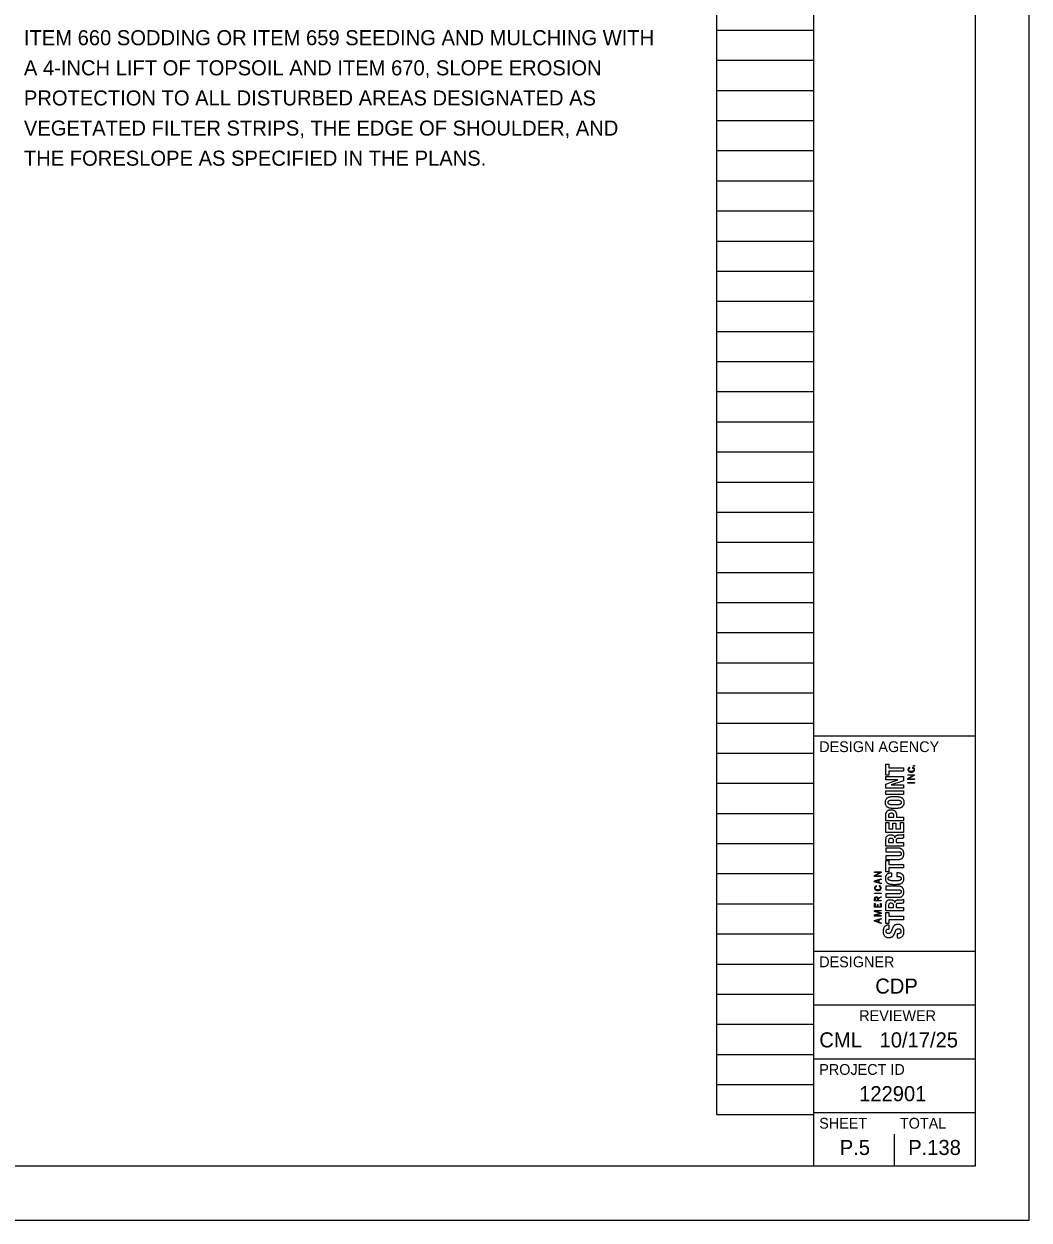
# Model space of a CAD drawing. Extents: x -19 to 64.6, y -1.7 to 22.
# Drawn here: x 24.66 to 34, y 0 to 11.12 of the extents above; entities that cross this region are included whole.
import ezdxf

# ---------------------------------------------------------------- set-up
doc = ezdxf.new("R2010")
doc.units = 0
for name, color, linetype in [('SH_Border', 7, 'Continuous'), ('SH_Cut_Line', 7, 'Continuous'), ('SH_Data', 7, 'Continuous'), ('SH_Text', 7, 'Continuous')]:
    doc.layers.add(name, color=color, linetype=linetype)

msp = doc.modelspace()

# ---------------------------------------------------------------- linework, layer by layer
at = {"layer": 'SH_Border'}
for p, q in [((32, 0.5), (32, 21.5)), ((32, 4.5), (33.5, 4.5)), ((32, 2.5), (33.5, 2.5)), ((32, 2), (33.5, 2)), ((32, 1.5), (33.5, 1.5)), ((32, 1), (33.5, 1))]:
    msp.add_line(p, q, dxfattribs=at)
msp.add_lwpolyline([(1.5, 21.5), (33.5, 21.5), (33.5, 0.5), (1.5, 0.5)], close=True, dxfattribs=at)
at = {"layer": 'SH_Cut_Line'}
msp.add_lwpolyline([(0, 0), (34, 0), (34, 22), (0, 22)], close=True, dxfattribs=at)
at = {"layer": 'SH_Data'}
for p, q in [((31.1, 0.98), (31.1, 21.14)), ((32, 0.98), (32, 21.14)), ((31.1, 11.06), (32, 11.06)), ((31.1, 10.78), (32, 10.78)), ((31.1, 10.5), (32, 10.5)), ((31.1, 10.22), (32, 10.22)), ((31.1, 9.94), (32, 9.94)), ((31.1, 9.66), (32, 9.66)), ((31.1, 9.38), (32, 9.38)), ((31.1, 9.1), (32, 9.1)), ((31.1, 8.82), (32, 8.82)), ((31.1, 8.54), (32, 8.54)), ((31.1, 8.26), (32, 8.26)), ((31.1, 7.98), (32, 7.98)), ((31.1, 7.7), (32, 7.7)), ((31.1, 7.42), (32, 7.42)), ((31.1, 7.14), (32, 7.14)), ((31.1, 6.86), (32, 6.86)), ((31.1, 6.58), (32, 6.58)), ((31.1, 6.3), (32, 6.3)), ((31.1, 6.02), (32, 6.02)), ((31.1, 5.74), (32, 5.74)), ((31.1, 5.46), (32, 5.46)), ((31.1, 5.18), (32, 5.18)), ((31.1, 4.9), (32, 4.9)), ((31.1, 4.62), (32, 4.62)), ((31.1, 4.34), (32, 4.34)), ((31.1, 4.06), (32, 4.06)), ((31.1, 3.78), (32, 3.78)), ((31.1, 3.5), (32, 3.5)), ((32.75, 3.5), (32.75, 3.5)), ((32.75, 3.5), (32.75, 3.5)), ((31.1, 3.22), (32, 3.22)), ((31.1, 2.94), (32, 2.94)), ((31.1, 2.66), (32, 2.66)), ((31.1, 2.38), (32, 2.38)), ((31.1, 2.1), (32, 2.1)), ((31.1, 1.82), (32, 1.82)), ((31.1, 1.54), (32, 1.54)), ((31.1, 1.26), (32, 1.26)), ((31.1, 0.98), (32, 0.98)), ((32.75, 0.5), (32.75, 0.8)), ((32.375, 0.675), (32.375, 0.675))]:
    msp.add_line(p, q, dxfattribs=at)
for points in [[(32.67, 4.239), (32.697, 4.239), (32.697, 4.204), (32.833, 4.204), (32.833, 4.171), (32.697, 4.171), (32.697, 4.135), (32.67, 4.135), (32.67, 4.239)], [(32.935, 4.218), (32.927, 4.218), (32.927, 4.225), (32.935, 4.225), (32.935, 4.218)], [(32.67, 4.051), (32.781, 4.091), (32.781, 4.092), (32.67, 4.092), (32.67, 4.122), (32.833, 4.122), (32.833, 4.084), (32.719, 4.044), (32.719, 4.044), (32.833, 4.044), (32.833, 4.013), (32.67, 4.013), (32.67, 4.051)], [(32.875, 4.096), (32.875, 4.105), (32.925, 4.134), (32.925, 4.134), (32.875, 4.134), (32.875, 4.139), (32.935, 4.139), (32.935, 4.134), (32.88, 4.102), (32.88, 4.101), (32.935, 4.101), (32.935, 4.096), (32.875, 4.096)], [(32.875, 4.061), (32.875, 4.067), (32.935, 4.067), (32.935, 4.061), (32.875, 4.061)], [(32.833, 3.957), (32.67, 3.957), (32.67, 3.99), (32.833, 3.99), (32.833, 3.957)], [(32.833, 3.712), (32.67, 3.712), (32.67, 3.769)], [(32.67, 3.694), (32.697, 3.694), (32.697, 3.635), (32.735, 3.635), (32.735, 3.69), (32.762, 3.69), (32.762, 3.635), (32.806, 3.635), (32.806, 3.696), (32.833, 3.696), (32.833, 3.603), (32.67, 3.603), (32.67, 3.694)], [(32.694, 3.744), (32.743, 3.744), (32.743, 3.759)], [(32.694, 3.758), (32.694, 3.744)], [(32.768, 3.762), (32.768, 3.744), (32.833, 3.744), (32.833, 3.712)], [(32.832, 3.587), (32.833, 3.587), (32.833, 3.552)], [(32.833, 3.476), (32.67, 3.476), (32.67, 3.537)], [(32.694, 3.525), (32.694, 3.509)], [(32.694, 3.509), (32.741, 3.509), (32.741, 3.523)], [(32.752, 3.554), (32.752, 3.554)], [(32.764, 3.527), (32.764, 3.509), (32.833, 3.509), (32.833, 3.476)], [(32.816, 3.548), (32.784, 3.547)], [(32.67, 3.341), (32.697, 3.341), (32.697, 3.305), (32.833, 3.305), (32.833, 3.273), (32.697, 3.273), (32.697, 3.237), (32.67, 3.237), (32.67, 3.341)], [(32.565, 3.194), (32.565, 3.203), (32.615, 3.231), (32.615, 3.231), (32.565, 3.231), (32.565, 3.237), (32.625, 3.237), (32.625, 3.231), (32.569, 3.199), (32.569, 3.199), (32.625, 3.199), (32.625, 3.194), (32.565, 3.194)], [(32.625, 3.125), (32.565, 3.144), (32.565, 3.152), (32.625, 3.171), (32.625, 3.165), (32.605, 3.159), (32.605, 3.137), (32.625, 3.131), (32.625, 3.125)], [(32.601, 3.138), (32.601, 3.158), (32.569, 3.148), (32.569, 3.148), (32.601, 3.138)], [(32.565, 3.034), (32.565, 3.039), (32.625, 3.039), (32.625, 3.034), (32.565, 3.034)], [(32.596, 2.992), (32.625, 3.006), (32.625, 3), (32.597, 2.987), (32.597, 2.971), (32.625, 2.971), (32.625, 2.966), (32.565, 2.966), (32.565, 2.986)], [(32.625, 2.907), (32.565, 2.907), (32.565, 2.941), (32.569, 2.941), (32.569, 2.913), (32.591, 2.913), (32.591, 2.933), (32.596, 2.933), (32.596, 2.913), (32.62, 2.913), (32.62, 2.943), (32.625, 2.943), (32.625, 2.907)], [(32.569, 2.971), (32.593, 2.971), (32.593, 2.986)], [(32.569, 2.986), (32.569, 2.971)], [(32.833, 2.873), (32.67, 2.873), (32.67, 2.934)], [(32.694, 2.922), (32.694, 2.906)], [(32.694, 2.906), (32.741, 2.906), (32.741, 2.92)], [(32.752, 2.951), (32.752, 2.951)], [(32.764, 2.924), (32.764, 2.906), (32.833, 2.906), (32.833, 2.873)], [(32.816, 2.944), (32.784, 2.944)], [(32.832, 2.984), (32.833, 2.984), (32.833, 2.949)], [(32.625, 2.826), (32.565, 2.826), (32.565, 2.836), (32.615, 2.852), (32.615, 2.853), (32.565, 2.869), (32.565, 2.879), (32.625, 2.879), (32.625, 2.873), (32.569, 2.873), (32.569, 2.873), (32.625, 2.855), (32.625, 2.85), (32.569, 2.832), (32.569, 2.832), (32.625, 2.832), (32.625, 2.826)], [(32.625, 2.758), (32.565, 2.777), (32.565, 2.785), (32.625, 2.804), (32.625, 2.798), (32.605, 2.792), (32.605, 2.769), (32.625, 2.763), (32.625, 2.758)], [(32.601, 2.771), (32.601, 2.791), (32.569, 2.781), (32.569, 2.781), (32.601, 2.771)], [(32.67, 2.86), (32.697, 2.86), (32.697, 2.824), (32.833, 2.824), (32.833, 2.791), (32.697, 2.791), (32.697, 2.756), (32.67, 2.756), (32.67, 2.86)]]:
    msp.add_lwpolyline(points, dxfattribs=at)
for points in [[(32.893, 4.201), (32.889, 4.199), (32.885, 4.197), (32.883, 4.195), (32.88, 4.193), (32.879, 4.19), (32.879, 4.186), (32.879, 4.183), (32.88, 4.181), (32.881, 4.178), (32.882, 4.176), (32.884, 4.175), (32.887, 4.173), (32.889, 4.172), (32.892, 4.171), (32.895, 4.17), (32.898, 4.169), (32.902, 4.169), (32.905, 4.169), (32.909, 4.169), (32.912, 4.169), (32.915, 4.17), (32.919, 4.171), (32.921, 4.172), (32.924, 4.173), (32.926, 4.175), (32.928, 4.176), (32.929, 4.179), (32.931, 4.181), (32.931, 4.184), (32.931, 4.187), (32.931, 4.189), (32.931, 4.191), (32.93, 4.193), (32.929, 4.194), (32.928, 4.196), (32.927, 4.197), (32.926, 4.198), (32.924, 4.199), (32.922, 4.2), (32.921, 4.2), (32.919, 4.201), (32.917, 4.202), (32.917, 4.202), (32.918, 4.207), (32.918, 4.207), (32.92, 4.206), (32.923, 4.205), (32.925, 4.204), (32.927, 4.203), (32.929, 4.202), (32.931, 4.2), (32.932, 4.199), (32.934, 4.197), (32.934, 4.195), (32.935, 4.192), (32.936, 4.19), (32.936, 4.187), (32.936, 4.183), (32.935, 4.18), (32.934, 4.177), (32.932, 4.174), (32.93, 4.172), (32.927, 4.17), (32.925, 4.168), (32.921, 4.166), (32.918, 4.165), (32.914, 4.164), (32.91, 4.164), (32.905, 4.164), (32.901, 4.164), (32.896, 4.164), (32.893, 4.165), (32.889, 4.166), (32.886, 4.168), (32.883, 4.17), (32.88, 4.172), (32.878, 4.174), (32.877, 4.177), (32.875, 4.18), (32.875, 4.183), (32.875, 4.187), (32.875, 4.189), (32.875, 4.192), (32.876, 4.194), (32.877, 4.196), (32.878, 4.198), (32.88, 4.199), (32.881, 4.201), (32.883, 4.202), (32.885, 4.203), (32.887, 4.204), (32.889, 4.205), (32.892, 4.206), (32.892, 4.206), (32.893, 4.201), (32.893, 4.201)], [(32.751, 3.826), (32.739, 3.826), (32.727, 3.826), (32.717, 3.828), (32.706, 3.829), (32.697, 3.831), (32.69, 3.835), (32.682, 3.839), (32.677, 3.845), (32.672, 3.852), (32.668, 3.859), (32.666, 3.869), (32.666, 3.882), (32.666, 3.894), (32.668, 3.904), (32.672, 3.911), (32.677, 3.918), (32.682, 3.924), (32.69, 3.928), (32.697, 3.932), (32.706, 3.934), (32.717, 3.936), (32.727, 3.937), (32.739, 3.937), (32.751, 3.937), (32.758, 3.937), (32.764, 3.937), (32.771, 3.937)], [(32.751, 3.859), (32.762, 3.859), (32.771, 3.859), (32.779, 3.859), (32.787, 3.86), (32.793, 3.861), (32.798, 3.863), (32.803, 3.864), (32.806, 3.867), (32.808, 3.87), (32.81, 3.873), (32.812, 3.877), (32.812, 3.882), (32.812, 3.886), (32.81, 3.89), (32.808, 3.893), (32.806, 3.896), (32.803, 3.899), (32.798, 3.9), (32.793, 3.902), (32.787, 3.903), (32.779, 3.904), (32.771, 3.904), (32.762, 3.904), (32.751, 3.904), (32.74, 3.904), (32.731, 3.904), (32.723, 3.904), (32.716, 3.903), (32.709, 3.902), (32.704, 3.9), (32.7, 3.899), (32.696, 3.896), (32.694, 3.893), (32.692, 3.89), (32.691, 3.886), (32.691, 3.882), (32.691, 3.877), (32.692, 3.873), (32.694, 3.87), (32.696, 3.867), (32.7, 3.864), (32.704, 3.863), (32.709, 3.861), (32.716, 3.86), (32.723, 3.859), (32.731, 3.859), (32.74, 3.859), (32.751, 3.859)], [(32.771, 3.937), (32.776, 3.936), (32.781, 3.936), (32.785, 3.936), (32.796, 3.934), (32.805, 3.932), (32.812, 3.928), (32.82, 3.924), (32.825, 3.918), (32.83, 3.911), (32.834, 3.904), (32.836, 3.894), (32.836, 3.882), (32.836, 3.869), (32.834, 3.859), (32.83, 3.852), (32.825, 3.845), (32.82, 3.839), (32.812, 3.835), (32.805, 3.831), (32.796, 3.829), (32.785, 3.828), (32.775, 3.826), (32.763, 3.826), (32.751, 3.826)], [(32.67, 3.769), (32.67, 3.777), (32.671, 3.784), (32.674, 3.79), (32.677, 3.796), (32.68, 3.8), (32.685, 3.804), (32.689, 3.807), (32.695, 3.81), (32.701, 3.812), (32.706, 3.813), (32.712, 3.814), (32.719, 3.814), (32.727, 3.814), (32.734, 3.813), (32.741, 3.81), (32.747, 3.808), (32.752, 3.804), (32.756, 3.8), (32.76, 3.795), (32.763, 3.79), (32.765, 3.783), (32.767, 3.777), (32.768, 3.77), (32.768, 3.762)], [(32.743, 3.759), (32.743, 3.766), (32.741, 3.771), (32.737, 3.775), (32.733, 3.779), (32.727, 3.781), (32.719, 3.781), (32.711, 3.781), (32.705, 3.779), (32.7, 3.776), (32.696, 3.772), (32.694, 3.766), (32.694, 3.758)], [(32.67, 3.537), (32.67, 3.551), (32.673, 3.562), (32.68, 3.569), (32.687, 3.577), (32.698, 3.581), (32.712, 3.581), (32.723, 3.581), (32.732, 3.579), (32.739, 3.574), (32.745, 3.57), (32.75, 3.563), (32.752, 3.554)], [(32.752, 3.554), (32.753, 3.559), (32.755, 3.564), (32.757, 3.567), (32.759, 3.571), (32.762, 3.573), (32.766, 3.575), (32.769, 3.577), (32.774, 3.578), (32.78, 3.579), (32.786, 3.58), (32.794, 3.58), (32.802, 3.58), (32.811, 3.58), (32.818, 3.581), (32.822, 3.582), (32.827, 3.582), (32.83, 3.584), (32.832, 3.587)], [(32.67, 3.385), (32.67, 3.385), (32.783, 3.385), (32.783, 3.385), (32.787, 3.385), (32.791, 3.385), (32.795, 3.386), (32.798, 3.387), (32.801, 3.388), (32.803, 3.389), (32.806, 3.39), (32.808, 3.392), (32.809, 3.395), (32.811, 3.397), (32.812, 3.401), (32.812, 3.404), (32.812, 3.408), (32.811, 3.411), (32.809, 3.414), (32.808, 3.417), (32.806, 3.418), (32.803, 3.42), (32.801, 3.421), (32.798, 3.422), (32.795, 3.423), (32.791, 3.423), (32.787, 3.424), (32.783, 3.424), (32.783, 3.424), (32.67, 3.424), (32.67, 3.424), (32.67, 3.424), (32.67, 3.457), (32.67, 3.457), (32.67, 3.457), (32.783, 3.457), (32.783, 3.457), (32.794, 3.457), (32.802, 3.455), (32.809, 3.452), (32.816, 3.449), (32.821, 3.445), (32.825, 3.441), (32.829, 3.436), (32.832, 3.43), (32.834, 3.424), (32.835, 3.418), (32.836, 3.411), (32.836, 3.404), (32.836, 3.398), (32.835, 3.391), (32.834, 3.385), (32.833, 3.379), (32.83, 3.373), (32.826, 3.368), (32.822, 3.363), (32.817, 3.36), (32.81, 3.357), (32.803, 3.354), (32.794, 3.352), (32.783, 3.352), (32.783, 3.352), (32.67, 3.352), (32.67, 3.352), (32.67, 3.352), (32.67, 3.385), (32.67, 3.385)], [(32.741, 3.523), (32.741, 3.531), (32.739, 3.537), (32.735, 3.542), (32.732, 3.546), (32.725, 3.548), (32.717, 3.548), (32.702, 3.548), (32.694, 3.54), (32.694, 3.525)], [(32.784, 3.547), (32.778, 3.546), (32.773, 3.545), (32.769, 3.542), (32.766, 3.539), (32.764, 3.534), (32.764, 3.527)], [(32.833, 3.552), (32.831, 3.55), (32.828, 3.549), (32.825, 3.549), (32.822, 3.548), (32.819, 3.548), (32.816, 3.548)], [(32.725, 3.193), (32.713, 3.193), (32.704, 3.192), (32.699, 3.189), (32.693, 3.186), (32.691, 3.181), (32.691, 3.174), (32.691, 3.17), (32.692, 3.166), (32.694, 3.163), (32.696, 3.161), (32.7, 3.159), (32.705, 3.157), (32.71, 3.156), (32.716, 3.155), (32.724, 3.154), (32.732, 3.153), (32.742, 3.153), (32.753, 3.153), (32.766, 3.153), (32.776, 3.153), (32.783, 3.154), (32.791, 3.155), (32.797, 3.156), (32.801, 3.158), (32.805, 3.16), (32.808, 3.162), (32.809, 3.165), (32.811, 3.168), (32.812, 3.171), (32.812, 3.174), (32.812, 3.177), (32.811, 3.18), (32.81, 3.182), (32.809, 3.185), (32.807, 3.187), (32.804, 3.189), (32.801, 3.191), (32.797, 3.192), (32.792, 3.193), (32.786, 3.194), (32.779, 3.195), (32.77, 3.195), (32.77, 3.195), (32.77, 3.228), (32.77, 3.228), (32.779, 3.228), (32.787, 3.227), (32.795, 3.226), (32.803, 3.224), (32.81, 3.222), (32.816, 3.218), (32.822, 3.214), (32.827, 3.209), (32.831, 3.202), (32.834, 3.196), (32.836, 3.187), (32.836, 3.176), (32.836, 3.163), (32.834, 3.154), (32.83, 3.146), (32.825, 3.139), (32.82, 3.133), (32.812, 3.129), (32.805, 3.126), (32.796, 3.123), (32.785, 3.122), (32.775, 3.121), (32.763, 3.12), (32.751, 3.12), (32.739, 3.12), (32.727, 3.121), (32.717, 3.122), (32.706, 3.123), (32.697, 3.126), (32.69, 3.129), (32.682, 3.133), (32.677, 3.139), (32.672, 3.146), (32.668, 3.154), (32.666, 3.163), (32.666, 3.176), (32.666, 3.188), (32.668, 3.197), (32.672, 3.204), (32.676, 3.21), (32.681, 3.215), (32.687, 3.219), (32.692, 3.222), (32.699, 3.224), (32.706, 3.225), (32.712, 3.226), (32.719, 3.226), (32.725, 3.226), (32.725, 3.226), (32.725, 3.193), (32.725, 3.193)], [(32.582, 3.101), (32.578, 3.1), (32.575, 3.098), (32.572, 3.095), (32.57, 3.093), (32.569, 3.09), (32.569, 3.086), (32.569, 3.083), (32.569, 3.081), (32.571, 3.079), (32.572, 3.077), (32.574, 3.075), (32.576, 3.074), (32.579, 3.072), (32.581, 3.071), (32.585, 3.07), (32.588, 3.07), (32.591, 3.069), (32.595, 3.069), (32.598, 3.069), (32.602, 3.07), (32.605, 3.07), (32.608, 3.071), (32.611, 3.072), (32.613, 3.074), (32.616, 3.075), (32.618, 3.077), (32.619, 3.079), (32.62, 3.081), (32.621, 3.084), (32.621, 3.087), (32.621, 3.089), (32.62, 3.091), (32.62, 3.093), (32.619, 3.095), (32.618, 3.096), (32.617, 3.097), (32.615, 3.098), (32.614, 3.099), (32.612, 3.1), (32.61, 3.101), (32.608, 3.102), (32.606, 3.102), (32.606, 3.102), (32.607, 3.107), (32.607, 3.107), (32.61, 3.107), (32.612, 3.106), (32.615, 3.105), (32.617, 3.104), (32.619, 3.102), (32.62, 3.101), (32.622, 3.099), (32.623, 3.097), (32.624, 3.095), (32.625, 3.093), (32.625, 3.09), (32.625, 3.087), (32.625, 3.083), (32.625, 3.08), (32.623, 3.077), (32.622, 3.074), (32.62, 3.072), (32.617, 3.07), (32.614, 3.068), (32.611, 3.067), (32.607, 3.066), (32.604, 3.065), (32.599, 3.064), (32.595, 3.064), (32.59, 3.064), (32.586, 3.065), (32.582, 3.066), (32.579, 3.067), (32.575, 3.068), (32.573, 3.07), (32.57, 3.072), (32.568, 3.074), (32.566, 3.077), (32.565, 3.08), (32.564, 3.083), (32.564, 3.087), (32.564, 3.09), (32.565, 3.092), (32.566, 3.094), (32.566, 3.096), (32.568, 3.098), (32.569, 3.099), (32.571, 3.101), (32.572, 3.102), (32.575, 3.103), (32.577, 3.104), (32.579, 3.105), (32.581, 3.106), (32.581, 3.106), (32.582, 3.101), (32.582, 3.101)], [(32.565, 2.986), (32.565, 2.992), (32.566, 2.996), (32.569, 2.999), (32.572, 3.003), (32.576, 3.004), (32.581, 3.004), (32.585, 3.004), (32.588, 3.003), (32.591, 3.001), (32.593, 2.999), (32.595, 2.996), (32.596, 2.992)], [(32.67, 3.032), (32.67, 3.032), (32.783, 3.032), (32.783, 3.032), (32.787, 3.032), (32.791, 3.033), (32.795, 3.033), (32.798, 3.034), (32.801, 3.035), (32.803, 3.036), (32.806, 3.038), (32.808, 3.04), (32.809, 3.042), (32.811, 3.045), (32.812, 3.048), (32.812, 3.052), (32.812, 3.056), (32.811, 3.059), (32.809, 3.061), (32.808, 3.064), (32.806, 3.066), (32.803, 3.067), (32.801, 3.069), (32.798, 3.07), (32.795, 3.07), (32.791, 3.071), (32.787, 3.071), (32.783, 3.071), (32.783, 3.071), (32.67, 3.071), (32.67, 3.071), (32.67, 3.071), (32.67, 3.104), (32.67, 3.104), (32.67, 3.104), (32.783, 3.104), (32.783, 3.104), (32.794, 3.104), (32.802, 3.102), (32.809, 3.1), (32.816, 3.097), (32.821, 3.093), (32.825, 3.088), (32.829, 3.083), (32.832, 3.077), (32.834, 3.071), (32.835, 3.065), (32.836, 3.058), (32.836, 3.052), (32.836, 3.045), (32.835, 3.039), (32.834, 3.032), (32.833, 3.026), (32.83, 3.021), (32.826, 3.016), (32.822, 3.011), (32.817, 3.007), (32.81, 3.004), (32.803, 3.001), (32.794, 3), (32.783, 3), (32.783, 3), (32.67, 3), (32.67, 3), (32.67, 3), (32.67, 3.032), (32.67, 3.032)], [(32.593, 2.986), (32.593, 2.99), (32.592, 2.993), (32.59, 2.995), (32.588, 2.997), (32.585, 2.999), (32.581, 2.999), (32.577, 2.999), (32.575, 2.998), (32.573, 2.995), (32.57, 2.993), (32.569, 2.99), (32.569, 2.986)], [(32.67, 2.934), (32.67, 2.948), (32.673, 2.958), (32.68, 2.966), (32.687, 2.974), (32.698, 2.978), (32.712, 2.978), (32.723, 2.978), (32.732, 2.975), (32.739, 2.971), (32.745, 2.967), (32.75, 2.96), (32.752, 2.951)], [(32.741, 2.92), (32.741, 2.928), (32.739, 2.934), (32.735, 2.938), (32.732, 2.943), (32.725, 2.945), (32.717, 2.945), (32.702, 2.945), (32.694, 2.937), (32.694, 2.922)], [(32.752, 2.951), (32.753, 2.956), (32.755, 2.961), (32.757, 2.964), (32.759, 2.967), (32.762, 2.97), (32.766, 2.972), (32.769, 2.974), (32.774, 2.975), (32.78, 2.976), (32.786, 2.976), (32.794, 2.977), (32.802, 2.977), (32.811, 2.977), (32.818, 2.978), (32.822, 2.978), (32.827, 2.979), (32.83, 2.981), (32.832, 2.984)], [(32.784, 2.944), (32.778, 2.943), (32.773, 2.942), (32.769, 2.939), (32.766, 2.936), (32.764, 2.931), (32.764, 2.924)], [(32.833, 2.949), (32.831, 2.947), (32.828, 2.946), (32.825, 2.945), (32.822, 2.945), (32.819, 2.945), (32.816, 2.944)], [(32.775, 2.661), (32.775, 2.661), (32.781, 2.661), (32.781, 2.661), (32.785, 2.661), (32.789, 2.662), (32.793, 2.662), (32.796, 2.663), (32.799, 2.664), (32.801, 2.666), (32.804, 2.668), (32.806, 2.671), (32.807, 2.674), (32.809, 2.677), (32.809, 2.681), (32.809, 2.686), (32.809, 2.692), (32.807, 2.697), (32.804, 2.701), (32.8, 2.706), (32.794, 2.708), (32.786, 2.708), (32.782, 2.708), (32.779, 2.708), (32.776, 2.707), (32.773, 2.705), (32.77, 2.704), (32.767, 2.701), (32.765, 2.698), (32.763, 2.695), (32.761, 2.691), (32.759, 2.687), (32.757, 2.681), (32.755, 2.675), (32.752, 2.667), (32.749, 2.66), (32.745, 2.654), (32.742, 2.647), (32.738, 2.642), (32.734, 2.638), (32.73, 2.634), (32.725, 2.631), (32.719, 2.629), (32.713, 2.628), (32.706, 2.627), (32.699, 2.627), (32.68, 2.627), (32.667, 2.632), (32.658, 2.642), (32.649, 2.652), (32.644, 2.666), (32.644, 2.684), (32.644, 2.692), (32.645, 2.7), (32.647, 2.707), (32.649, 2.714), (32.651, 2.72), (32.656, 2.725), (32.66, 2.73), (32.665, 2.734), (32.671, 2.737), (32.677, 2.74), (32.685, 2.741), (32.694, 2.741), (32.694, 2.741), (32.699, 2.741), (32.699, 2.741), (32.699, 2.741), (32.699, 2.705), (32.699, 2.705), (32.69, 2.705), (32.683, 2.704), (32.679, 2.701), (32.674, 2.697), (32.671, 2.692), (32.671, 2.685), (32.671, 2.681), (32.672, 2.678), (32.673, 2.675), (32.675, 2.672), (32.676, 2.67), (32.678, 2.668), (32.68, 2.667), (32.682, 2.665), (32.685, 2.665), (32.688, 2.664), (32.69, 2.664), (32.693, 2.664), (32.699, 2.664), (32.704, 2.665), (32.707, 2.668), (32.711, 2.67), (32.715, 2.675), (32.718, 2.683), (32.718, 2.683), (32.731, 2.712), (32.731, 2.712), (32.734, 2.719), (32.737, 2.725), (32.74, 2.729), (32.744, 2.734), (32.747, 2.737), (32.751, 2.74), (32.755, 2.743), (32.76, 2.745), (32.764, 2.746), (32.769, 2.747), (32.774, 2.747), (32.78, 2.747), (32.799, 2.747), (32.814, 2.742), (32.823, 2.73), (32.832, 2.719), (32.837, 2.703), (32.837, 2.683), (32.837, 2.662), (32.832, 2.647), (32.823, 2.638), (32.813, 2.628), (32.8, 2.624), (32.783, 2.624), (32.783, 2.624), (32.775, 2.624), (32.775, 2.624), (32.775, 2.624), (32.775, 2.661), (32.775, 2.661)]]:
    msp.add_open_spline(points, degree=3, dxfattribs=at)

# ---------------------------------------------------------------- texts
for s, height, p in [('DESIGN AGENCY', 0.1, (32.05, 4.35)), ('DESIGNER', 0.1, (32.05, 2.35)), ('CDP', 0.14, (32.571, 2.105)), ('REVIEWER', 0.1, (32.422, 1.85)), ('CML', 0.14, (32.051, 1.605)), ('10/17/25', 0.14, (32.611, 1.605)), ('PROJECT ID', 0.1, (32.05, 1.35)), ('122901', 0.14, (32.421, 1.105)), ('SHEET', 0.1, (32.05, 0.85)), ('TOTAL', 0.1, (32.8, 0.85)), ('P.5', 0.14, (32.241, 0.605)), ('P.138', 0.14, (32.877, 0.605))]:
    msp.add_text(s, height=height, dxfattribs=at).set_placement(p)
at = {"layer": 'SH_Text'}
for s, p in [('ITEM 660 SODDING OR ITEM 659 SEEDING AND MULCHING WITH', (24.66, 10.92)), ('A 4-INCH LIFT OF TOPSOIL AND ITEM 670, SLOPE EROSION', (24.66, 10.64)), ('PROTECTION TO ALL DISTURBED AREAS DESIGNATED AS', (24.66, 10.36)), ('VEGETATED FILTER STRIPS, THE EDGE OF SHOULDER, AND', (24.66, 10.08)), ('THE FORESLOPE AS SPECIFIED IN THE PLANS.', (24.66, 9.8))]:
    msp.add_text(s, height=0.14, dxfattribs=at).set_placement(p)

doc.saveas('drawing.dxf')
